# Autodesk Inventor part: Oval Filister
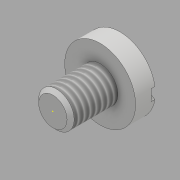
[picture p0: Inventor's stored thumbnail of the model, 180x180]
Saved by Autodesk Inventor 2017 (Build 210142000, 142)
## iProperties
Created: 2016-06
Part Number: Oval Filister
Material: Generic
Document SubType Name: Modeling
Designer: CADCIM
Density: 1 g/cm^3
Appearance: Default
Author: CADCIM
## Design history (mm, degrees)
sketch "Sketch1"
  geometry: 1 further point
sketch "Sketch2"
  geometry: C1 r 3 at (0, 0); 1 further point
  constraints: 1 centre point, 1 coincident
  dimensions: "d0" = 6 diameter of C1
extrude "Extrusion1" new body sketch "Sketch2" distance "d1" = 8; taper "d2" = 0 deg
sketch "Sketch3"
  geometry: 1 further point
sketch "Sketch4"
  geometry: L1 (8, 0)-(8, -6); L2 (8, -3)-(8, 3) reference; L3 (8, -6)-(11.35, -6); L4 (12.6, 0)-(8, 0); A1 r 15.025 centre (-2.425, 0) between (11.35, -6) and (12.6, 0); 2 further points
  constraints: 6 end point, 2 midpoint, 2 point on circle, 1 centre point, 1 horizontal, 1 horizontal alignment, 1 perpendicular, 1 point on line, 1 vertical
  dimensions: "d3" = 6 distance of L1.start L1.end; "d4" = 4.6 distance of L4.start L1.start; "d5" = 1.25 horizontal distance of L3.end L4.start
revolve "Revolution1" sketch "Sketch4" stored, may be unused: angle "d6" = 90 deg
workplane "Work Plane1"
sketch "Sketch5"
  geometry: L1 (6.611, -0.95)-(-6.611, -0.95); L2 (-6.611, -0.95)-(-6.611, 0.95); L3 (-6.611, 0.95)-(6.611, 0.95); L4 (6.611, 0.95)-(6.611, -0.95); L5 (6.611, 0)-(-6.611, 0); 2 further points
  constraints: 10 end point, 3 midpoint, 2 parallel, 1 coincident, 1 horizontal, 1 perpendicular
  dimensions: "d8" = 1.9 distance of L3.end L1.start
extrude "Extrusion2" cut sketch "Sketch5" distance "d9" = 1.9; taper "d10" = 0 deg
thread "Thread1" dims "d11" = 10, "d12" = 0
chamfer "Chamfer1" distance "d13" = 0.6; stored, may be unused: second distance "d14" = 2, angle "d15" = 45 deg
body "Solid1"
other parameters: "d7" = -4.6
